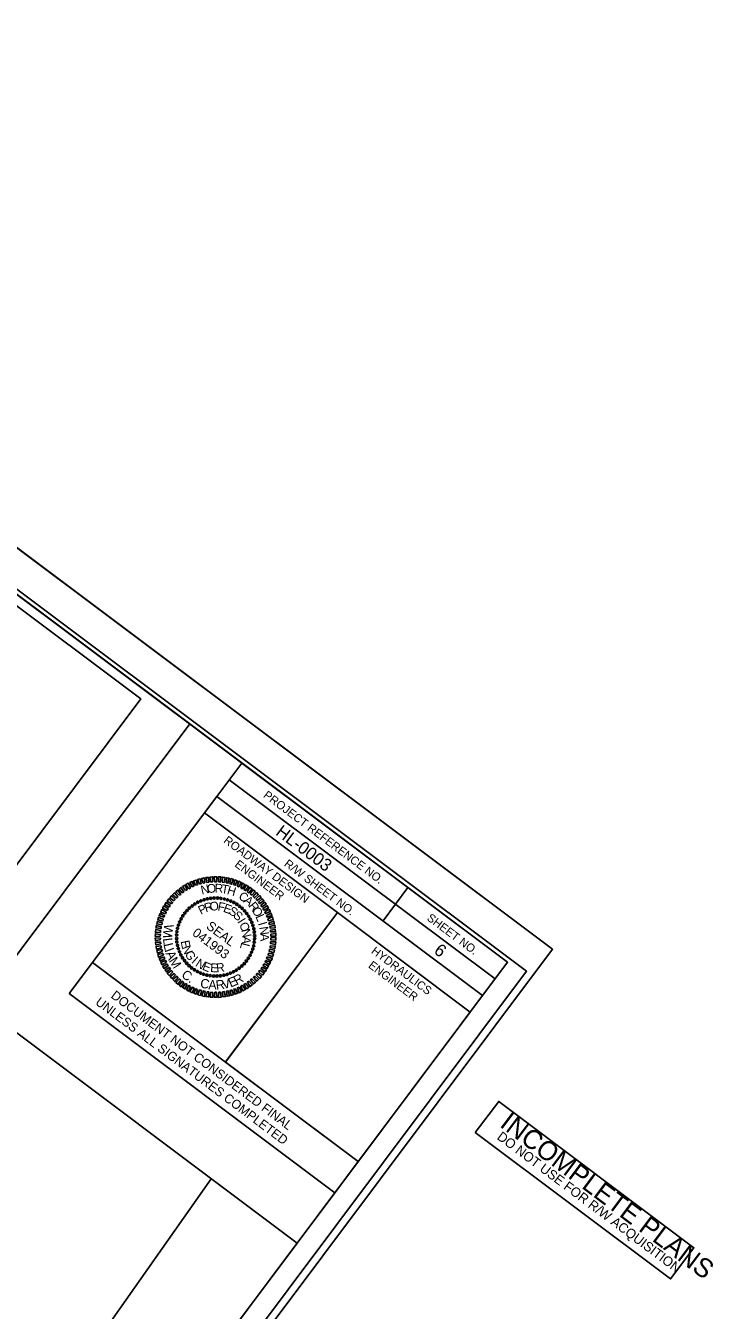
# Model space of a CAD drawing. Extents: x 928111 to 937215, y 684180 to 686530.
# Drawn here: x 931876 to 932290, y 684839 to 685613 of the extents above; entities that cross this region are included whole.
import ezdxf

# ---------------------------------------------------------------- set-up
doc = ezdxf.new("R2010")
doc.units = 0
for name, color, linetype in [('Default', 7, 'Continuous'), ('Matchline', 7, 'Continuous'), ('Prop DSN Text', 7, 'Continuous'), ('Sheet Cutting Line CELL', 7, 'Continuous'), ('Sheet Data Field CELL', 7, 'Continuous'), ('Sheet Layout Plan Border', 7, 'Continuous'), ('Sheet Plan CELL', 7, 'Continuous'), ('Sheet Plan Layout CELL', 7, 'Continuous'), ('Sheet Plot Border Inside CELL', 7, 'Continuous'), ('Sheet Plot Border Outside CELL', 7, 'Continuous')]:
    doc.layers.add(name, color=color, linetype=linetype)

msp = doc.modelspace()

# ---------------------------------------------------------------- linework, layer by layer
at = {"layer": 'Default'}
for p, q in [((931979.89, 685084.68), (931979.89, 685084.68)), ((931981.73, 685085.58), (931981.73, 685085.58)), ((931983.68, 685086.23), (931983.68, 685086.23)), ((931985.68, 685086.78), (931985.68, 685086.78)), ((931987.68, 685087.1), (931987.68, 685087.1)), ((931989.76, 685087.3), (931989.76, 685087.3)), ((931991.77, 685087.25), (931991.77, 685087.25)), ((931993.84, 685087.05), (931993.84, 685087.05)), ((931995.87, 685086.7), (931995.87, 685086.7)), ((931997.82, 685086.18), (931997.82, 685086.18)), ((931999.73, 685085.45), (931999.73, 685085.45)), ((932001.61, 685084.51), (932001.61, 685084.51)), ((931972.04, 685078.2), (931972.04, 685078.2)), ((931973.39, 685079.76), (931973.39, 685079.76)), ((931974.86, 685081.18), (931974.86, 685081.18)), ((931976.38, 685082.5), (931976.38, 685082.5)), ((931978.09, 685083.69), (931978.09, 685083.69)), ((932003.39, 685083.53), (932003.39, 685083.53)), ((932005.07, 685082.33), (932005.07, 685082.33)), ((932006.63, 685080.98), (932006.63, 685080.98)), ((932008.05, 685079.51), (932008.05, 685079.51)), ((932009.37, 685077.99), (932009.37, 685077.99)), ((931967.67, 685069), (931967.67, 685069)), ((931968.19, 685070.95), (931968.19, 685070.95)), ((931968.92, 685072.86), (931968.92, 685072.86)), ((931969.86, 685074.74), (931969.86, 685074.74)), ((931970.84, 685076.52), (931970.84, 685076.52)), ((932010.56, 685076.28), (932010.56, 685076.28)), ((932011.55, 685074.48), (932011.55, 685074.48)), ((932012.45, 685072.64), (932012.45, 685072.64)), ((932013.1, 685070.69), (932013.1, 685070.69)), ((931967.07, 685062.89), (931967.07, 685062.89)), ((931967.12, 685064.9), (931967.12, 685064.9)), ((931967.32, 685066.97), (931967.32, 685066.97)), ((931990.62, 685063.75), (931990.62, 685063.75)), ((932013.65, 685068.69), (932013.65, 685068.69)), ((932013.97, 685066.7), (932013.97, 685066.7)), ((932014.12, 685062.6), (932014.12, 685062.6)), ((932014.17, 685064.61), (932014.17, 685064.61)), ((931967.27, 685060.81), (931967.27, 685060.81)), ((931967.59, 685058.81), (931967.59, 685058.81)), ((931968.14, 685056.81), (931968.14, 685056.81)), ((931968.79, 685054.86), (931968.79, 685054.86)), ((932012.32, 685054.64), (932012.32, 685054.64)), ((932013.05, 685056.55), (932013.05, 685056.55)), ((932013.57, 685058.5), (932013.57, 685058.5)), ((932013.92, 685060.53), (932013.92, 685060.53)), ((931969.69, 685053.02), (931969.69, 685053.02)), ((931970.69, 685051.22), (931970.69, 685051.22)), ((931971.87, 685049.51), (931971.87, 685049.51)), ((931973.19, 685047.99), (931973.19, 685047.99)), ((931974.61, 685046.52), (931974.61, 685046.52)), ((932006.38, 685046.32), (932006.38, 685046.32)), ((932007.85, 685047.74), (932007.85, 685047.74)), ((932009.2, 685049.3), (932009.2, 685049.3)), ((932010.4, 685050.98), (932010.4, 685050.98)), ((932011.38, 685052.76), (932011.38, 685052.76)), ((931976.17, 685045.17), (931976.17, 685045.17)), ((931977.85, 685043.97), (931977.85, 685043.97)), ((931979.63, 685042.99), (931979.63, 685042.99)), ((931981.51, 685042.05), (931981.51, 685042.05)), ((931983.42, 685041.32), (931983.42, 685041.32)), ((931985.37, 685040.8), (931985.37, 685040.8)), ((931987.4, 685040.45), (931987.4, 685040.45)), ((931989.47, 685040.25), (931989.47, 685040.25)), ((931991.48, 685040.2), (931991.48, 685040.2)), ((931993.57, 685040.4), (931993.57, 685040.4)), ((931995.56, 685040.72), (931995.56, 685040.72)), ((931997.56, 685041.27), (931997.56, 685041.27)), ((931999.51, 685041.92), (931999.51, 685041.92)), ((932001.35, 685042.82), (932001.35, 685042.82)), ((932003.15, 685043.82), (932003.15, 685043.82)), ((932004.86, 685045), (932004.86, 685045))]:
    msp.add_line(p, q, dxfattribs=at)
for points in [[(931987.63, 685096.97), (931987.22, 685099.86), (931988.79, 685100.09), (931988.74, 685096.97)], [(931990.01, 685097.01), (931989.74, 685100.02), (931991.34, 685100.05), (931991.08, 685096.97)], [(931992.27, 685097.07), (931992.32, 685100.02), (931993.83, 685100), (931993.44, 685096.9)], [(931994.63, 685096.77), (931994.76, 685099.84), (931996.37, 685099.57), (931995.68, 685096.69)], [(931970.54, 685090.34), (931968.58, 685092.57), (931969.77, 685093.61), (931971.43, 685090.9)], [(931972.45, 685091.72), (931970.63, 685094.13), (931971.99, 685094.93), (931973.45, 685092.2)], [(931974.44, 685092.81), (931972.76, 685095.41), (931974.19, 685096.15), (931975.43, 685093.35)], [(931976.48, 685093.97), (931975.04, 685096.51), (931976.48, 685097.25), (931977.46, 685094.34)], [(931978.59, 685094.91), (931977.33, 685097.61), (931978.87, 685098.09), (931979.69, 685095.13)], [(931980.84, 685095.56), (931979.77, 685098.36), (931981.29, 685098.91), (931981.86, 685095.91)], [(931983.03, 685096.15), (931982.18, 685099.07), (931983.73, 685099.43), (931984.06, 685096.43)], [(931985.41, 685096.59), (931984.65, 685099.56), (931986.24, 685099.72), (931986.46, 685096.74)], [(931996.91, 685096.46), (931997.29, 685099.46), (931998.84, 685099.12), (931997.99, 685096.18)], [(931999.16, 685096.01), (931999.81, 685098.92), (932001.27, 685098.53), (932000.26, 685095.54)], [(932001.44, 685095.24), (932002.27, 685098.13), (932003.68, 685097.6), (932002.43, 685094.91)], [(932003.61, 685094.37), (932004.59, 685097.33), (932006.06, 685096.64), (932004.54, 685093.97)], [(932005.72, 685093.44), (932006.92, 685096.29), (932008.24, 685095.47), (932006.7, 685092.88)], [(932007.69, 685092.31), (932009.07, 685095.02), (932010.46, 685094.22), (932008.67, 685091.75)], [(932009.7, 685091.1), (932011.34, 685093.68), (932012.55, 685092.71), (932010.58, 685090.38)], [(932011.48, 685089.71), (932013.3, 685092.15), (932014.51, 685091.18), (932012.35, 685089)], [(931962.62, 685081.8), (931959.96, 685083.33), (931960.84, 685084.66), (931963.22, 685082.76)], [(931963.99, 685083.71), (931961.46, 685085.42), (931962.42, 685086.7), (931964.66, 685084.61)], [(931965.43, 685085.55), (931963.05, 685087.46), (931964.05, 685088.64), (931966.18, 685086.4)], [(931966.97, 685087.21), (931964.73, 685089.24), (931965.84, 685090.4), (931967.83, 685087.97)], [(931968.7, 685088.9), (931966.6, 685090.95), (931967.82, 685092.02), (931969.59, 685089.47)], [(932013.27, 685088.19), (932015.25, 685090.52), (932016.31, 685089.37), (932014.06, 685087.37)], [(932014.84, 685086.54), (932016.98, 685088.69), (932018.08, 685087.58), (932015.66, 685085.76)], [(932016.45, 685084.7), (932018.65, 685086.85), (932019.7, 685085.6), (932017.1, 685083.92)], [(932017.88, 685082.86), (932020.19, 685084.76), (932021.07, 685083.52), (932018.47, 685082.01)], [(931959.58, 685075.64), (931956.54, 685076.58), (931957.24, 685077.99), (931959.91, 685076.63)], [(931960.48, 685077.78), (931957.59, 685078.84), (931958.32, 685080.28), (931960.85, 685078.74)], [(931961.49, 685079.83), (931958.66, 685081.14), (931959.51, 685082.5), (931962.02, 685080.85)], [(932019.07, 685080.92), (932021.7, 685082.64), (932022.41, 685081.4), (932019.73, 685080.01)], [(932020.22, 685078.94), (932022.82, 685080.45), (932023.59, 685079.06), (932020.74, 685077.91)], [(932021.3, 685076.79), (932023.91, 685078.17), (932024.56, 685076.68), (932021.67, 685075.8)], [(931957.73, 685068.95), (931954.65, 685069.21), (931955.03, 685070.74), (931957.81, 685070)], [(931958.19, 685071.12), (931955.13, 685071.66), (931955.54, 685073.22), (931958.43, 685072.23)], [(931958.83, 685073.39), (931955.82, 685074.13), (931956.27, 685075.6), (931959.05, 685074.46)], [(932022, 685074.68), (932024.95, 685075.87), (932025.33, 685074.35), (932022.49, 685073.61)], [(932022.7, 685072.4), (932025.63, 685073.42), (932025.99, 685071.87), (932023.02, 685071.34)], [(932023.25, 685070.17), (932026.25, 685070.97), (932026.48, 685069.39), (932023.54, 685069.07)], [(931957.29, 685064.3), (931954.27, 685064.1), (931954.38, 685065.72), (931957.38, 685065.35)], [(931957.32, 685061.99), (931954.33, 685061.6), (931954.3, 685063.2), (931957.36, 685063.14)], [(931957.47, 685066.57), (931954.41, 685066.63), (931954.54, 685068.29), (931957.51, 685067.71)], [(932023.62, 685067.84), (932026.55, 685068.4), (932026.78, 685066.82), (932023.73, 685066.82)], [(932023.95, 685063.2), (932026.97, 685063.4), (932026.87, 685061.78), (932023.86, 685062.15)], [(932023.92, 685065.51), (932026.91, 685065.9), (932026.94, 685064.3), (932023.88, 685064.37)], [(931957.62, 685059.66), (931954.69, 685059.1), (931954.46, 685060.68), (931957.51, 685060.68)], [(931957.99, 685057.33), (931954.99, 685056.53), (931954.76, 685058.11), (931957.7, 685058.43)], [(931958.54, 685055.1), (931955.61, 685054.08), (931955.25, 685055.63), (931958.22, 685056.16)], [(931959.24, 685052.82), (931956.29, 685051.63), (931955.91, 685053.15), (931958.75, 685053.89)], [(932022.41, 685054.11), (932025.43, 685053.37), (932024.97, 685051.9), (932022.19, 685053.04)], [(932023.05, 685056.38), (932026.11, 685055.84), (932025.7, 685054.28), (932022.81, 685055.27)], [(932023.51, 685058.55), (932026.59, 685058.29), (932026.21, 685056.76), (932023.43, 685057.5)], [(932023.77, 685060.93), (932026.83, 685060.87), (932026.7, 685059.21), (932023.73, 685059.79)], [(931959.94, 685050.71), (931957.33, 685049.34), (931956.68, 685050.82), (931959.57, 685051.7)], [(931961.02, 685048.56), (931958.42, 685047.05), (931957.66, 685048.44), (931960.5, 685049.59)], [(931962.18, 685046.58), (931959.54, 685044.86), (931958.83, 685046.1), (931961.51, 685047.49)], [(932018.62, 685045.7), (932021.29, 685044.17), (932020.4, 685042.84), (932018.02, 685044.74)], [(932019.75, 685047.67), (932022.58, 685046.36), (932021.74, 685045.01), (932019.22, 685046.65)], [(932020.76, 685049.72), (932023.66, 685048.66), (932022.92, 685047.22), (932020.39, 685048.76)], [(932021.66, 685051.86), (932024.7, 685050.92), (932024, 685049.52), (932021.33, 685050.87)], [(931963.36, 685044.64), (931961.05, 685042.74), (931960.17, 685043.98), (931962.77, 685045.49)], [(931964.79, 685042.8), (931962.59, 685040.65), (931961.54, 685041.9), (931964.15, 685043.58)], [(931966.4, 685040.96), (931964.26, 685038.81), (931963.16, 685039.93), (931965.58, 685041.75)], [(931967.97, 685039.31), (931966, 685036.98), (931964.93, 685038.14), (931967.18, 685040.13)], [(931969.76, 685037.79), (931967.94, 685035.35), (931966.73, 685036.32), (931968.89, 685038.5)], [(932012.54, 685038.6), (932014.64, 685036.55), (932013.42, 685035.48), (932011.65, 685038.03)], [(932014.27, 685040.29), (932016.51, 685038.26), (932015.4, 685037.1), (932013.41, 685039.53)], [(932015.81, 685041.95), (932018.19, 685040.04), (932017.19, 685038.86), (932015.06, 685041.1)], [(932017.25, 685043.79), (932019.78, 685042.08), (932018.82, 685040.8), (932016.58, 685042.89)], [(931971.54, 685036.4), (931969.9, 685033.83), (931968.69, 685034.79), (931970.66, 685037.12)], [(931973.55, 685035.19), (931972.17, 685032.48), (931970.78, 685033.28), (931972.57, 685035.75)], [(931975.52, 685034.06), (931974.32, 685031.21), (931973, 685032.03), (931974.54, 685034.62)], [(931977.63, 685033.13), (931976.65, 685030.17), (931975.18, 685030.87), (931976.7, 685033.53)], [(931979.8, 685032.26), (931978.97, 685029.37), (931977.56, 685029.9), (931978.81, 685032.59)], [(931982.09, 685031.49), (931981.43, 685028.58), (931979.97, 685028.97), (931980.98, 685031.96)], [(931984.33, 685031.04), (931983.95, 685028.04), (931982.4, 685028.38), (931983.25, 685031.32)], [(931986.61, 685030.73), (931986.48, 685027.66), (931984.87, 685027.94), (931985.56, 685030.81)], [(931988.97, 685030.43), (931988.92, 685027.48), (931987.41, 685027.5), (931987.8, 685030.6)], [(931991.24, 685030.49), (931991.5, 685027.48), (931989.9, 685027.45), (931990.16, 685030.53)], [(931993.61, 685030.53), (931994.02, 685027.64), (931992.45, 685027.41), (931992.5, 685030.54)], [(931995.83, 685030.91), (931996.59, 685027.94), (931995.01, 685027.78), (931994.78, 685030.76)], [(931998.21, 685031.35), (931999.06, 685028.43), (931997.51, 685028.07), (931997.18, 685031.07)], [(932000.4, 685031.94), (932001.47, 685029.14), (931999.95, 685028.59), (931999.38, 685031.59)], [(932002.65, 685032.59), (932003.91, 685029.89), (932002.37, 685029.41), (932001.55, 685032.37)], [(932004.76, 685033.53), (932006.2, 685030.99), (932004.76, 685030.25), (932003.78, 685033.16)], [(932006.81, 685034.7), (932008.48, 685032.09), (932007.05, 685031.35), (932005.81, 685034.15)], [(932008.79, 685035.78), (932010.61, 685033.37), (932009.25, 685032.57), (932007.79, 685035.3)], [(932010.7, 685037.16), (932012.66, 685034.93), (932011.47, 685033.89), (932009.81, 685036.6)]]:
    msp.add_lwpolyline(points, close=True, dxfattribs=at)
for centre, major_axis in [((931978.11, 685083.66), (-0.359, 0.571)), ((931979.89, 685084.67), (-0.308, 0.601)), ((931981.75, 685085.53), (-0.255, 0.625)), ((931983.68, 685086.22), (-0.199, 0.645)), ((931985.67, 685086.74), (-0.142, 0.66)), ((931987.69, 685087.08), (-0.084, 0.67)), ((931989.74, 685087.25), (-0.025, 0.675)), ((931991.79, 685087.23), (0.033, 0.674)), ((931993.83, 685087.04), (0.092, 0.669)), ((931995.85, 685086.67), (0.15, 0.658)), ((931997.83, 685086.13), (0.207, 0.643)), ((931999.75, 685085.42), (0.262, 0.622)), ((932001.6, 685084.54), (0.315, 0.597)), ((931970.87, 685076.5), (-0.567, 0.366)), ((931972.05, 685078.18), (-0.533, 0.414)), ((931973.38, 685079.74), (-0.495, 0.459)), ((931974.84, 685081.18), (-0.453, 0.5)), ((931976.42, 685082.49), (-0.408, 0.538)), ((932003.37, 685083.5), (0.366, 0.567)), ((932005.05, 685082.32), (0.414, 0.533)), ((932006.61, 685080.99), (0.459, 0.495)), ((932008.05, 685079.53), (0.5, 0.453)), ((932009.36, 685077.95), (0.538, 0.408)), ((932010.53, 685076.26), (0.571, 0.359)), ((931967.7, 685068.98), (-0.658, 0.15)), ((931968.24, 685070.96), (-0.643, 0.207)), ((931968.95, 685072.88), (-0.622, 0.262)), ((931969.83, 685074.73), (-0.597, 0.315)), ((932011.54, 685074.48), (0.601, 0.308)), ((932012.4, 685072.62), (0.625, 0.255)), ((932013.09, 685070.69), (0.645, 0.199)), ((932013.61, 685068.7), (0.66, 0.142)), ((931967.14, 685064.92), (-0.674, 0.033)), ((931967.12, 685062.87), (-0.675, -0.025)), ((931967.29, 685060.82), (-0.67, -0.084)), ((931967.33, 685066.96), (-0.669, 0.092)), ((932013.91, 685060.54), (0.669, -0.092)), ((932013.95, 685066.68), (0.67, 0.084)), ((932014.1, 685062.58), (0.674, -0.033)), ((932014.12, 685064.63), (0.675, 0.025)), ((931967.64, 685058.8), (-0.66, -0.142)), ((931968.15, 685056.81), (-0.645, -0.199)), ((931968.84, 685054.88), (-0.625, -0.255)), ((931969.7, 685053.02), (-0.601, -0.308)), ((932011.41, 685052.77), (0.597, -0.315)), ((932012.29, 685054.62), (0.622, -0.262)), ((932013, 685056.55), (0.643, -0.207)), ((932013.54, 685058.52), (0.658, -0.15)), ((931970.71, 685051.24), (-0.571, -0.359)), ((931971.88, 685049.55), (-0.538, -0.408)), ((931973.19, 685047.97), (-0.5, -0.453)), ((931974.63, 685046.51), (-0.459, -0.495)), ((931976.2, 685045.18), (-0.414, -0.533)), ((932004.82, 685045.01), (0.408, -0.538)), ((932006.4, 685046.32), (0.453, -0.5)), ((932007.86, 685047.76), (0.495, -0.459)), ((932009.19, 685049.33), (0.533, -0.414)), ((932010.37, 685051), (0.567, -0.366)), ((931977.87, 685044), (-0.366, -0.567)), ((931979.64, 685042.96), (-0.315, -0.597)), ((931981.49, 685042.08), (-0.262, -0.622)), ((931983.42, 685041.37), (-0.207, -0.643)), ((931985.39, 685040.83), (-0.15, -0.658)), ((931987.41, 685040.46), (-0.092, -0.669)), ((931989.45, 685040.27), (-0.033, -0.674)), ((931991.51, 685040.25), (0.025, -0.675)), ((931993.55, 685040.42), (0.084, -0.67)), ((931995.57, 685040.76), (0.142, -0.66)), ((931997.56, 685041.28), (0.199, -0.645)), ((931999.49, 685041.97), (0.255, -0.625)), ((932001.35, 685042.83), (0.308, -0.601)), ((932003.13, 685043.84), (0.359, -0.571))]:
    msp.add_ellipse(centre, major_axis=major_axis, ratio=0.999708, dxfattribs=at)
at = {"layer": 'Matchline'}
msp.add_line((931505.26, 684232.03), (931987.94, 684918.14), dxfattribs=at)
at = {"layer": 'Prop DSN Text'}
msp.add_lwpolyline([(931684.84, 685402.44), (931945.48, 685207.14), (931826.18, 685047.92), (931565.53, 685243.22)], close=True, dxfattribs=at)
at = {"layer": 'Sheet Cutting Line CELL'}
msp.add_line((932193.6, 685056.42), (930846.34, 686065.9), dxfattribs=at)
at = {"layer": 'Sheet Layout Plan Border'}
msp.add_line((931987.94, 684918.14), (931505.26, 684232.03), dxfattribs=at)
at = {"layer": 'Sheet Plan CELL'}
for p, q in [((931998.89, 685158.54), (932158.97, 685038.58)), ((931991.38, 685148.5), (931983.89, 685138.51)), ((931991.38, 685148.5), (932151.48, 685028.57)), ((931991.38, 685148.5), (932151.48, 685028.57)), ((932106.42, 685093.56), (932091.47, 685073.52)), ((932063.96, 685078.52), (931996.53, 684988.51)), ((931902.36, 685029.67), (931916.45, 685048.48)), ((931916.45, 685048.48), (932076.53, 684928.53)), ((932062.44, 684909.73), (931902.36, 685029.67)), ((932076.53, 684928.52), (932062.43, 684909.72))]:
    msp.add_line(p, q, dxfattribs=at)
for points in [[(932166.53, 685048.6), (930966.09, 685948.07), (930336.47, 685107.79), (931536.89, 684208.33)], [(931848.22, 685022.84), (932039.7, 684879.36), (932166.54, 685048.59), (931975.03, 685192.08)], [(932006.42, 685168.58), (932166.53, 685048.6), (932151.48, 685028.57), (931991.38, 685148.5)], [(931983.89, 685138.51), (932063.96, 685078.52), (931996.49, 684988.48), (931916.45, 685048.48)], [(932063.96, 685078.52), (932143.98, 685018.57), (932076.53, 684928.52), (931996.49, 684988.48)], [(932147.06, 684945.96), (932161.15, 684964.76), (932278.79, 684876.62), (932264.7, 684857.81)]]:
    msp.add_lwpolyline(points, close=True, dxfattribs=at)
at = {"layer": 'Sheet Plan Layout CELL'}
msp.add_lwpolyline([(930966.05, 685948.07), (930336.47, 685107.79), (931536.88, 684208.33), (932039.68, 684879.37), (931848.22, 685022.84), (931975.03, 685192.08)], close=True, dxfattribs=at)
at = {"layer": 'Sheet Plot Border Inside CELL'}
msp.add_lwpolyline([(930212.13, 685197.81), (931545.39, 684198.84), (932178, 685043.11), (930844.75, 686042.1)], close=True, dxfattribs=at)
at = {"layer": 'Sheet Plot Border Outside CELL'}
msp.add_lwpolyline([(930189.74, 685189.6), (931537, 684180.12), (932193.6, 685056.42), (930846.34, 686065.9)], close=True, dxfattribs=at)

# ---------------------------------------------------------------- texts
at = {"layer": 'Default'}
for s, height, rotation, p in [('N', 5.29, 12.57973, (931982.3, 685089.31)), ('O', 5.29, 5.37797, (931985.66, 685090.19)), ('R', 5.29, 358.17674, (931989.99, 685090.58)), ('T', 5.29, 350.976, (931993.78, 685090.32)), ('H', 5.29, 343.77571, (931997.14, 685089.73)), ('R', 5.29, 17.19588, (931984.74, 685078.58)), ('O', 5.29, 7.83747, (931987.44, 685079.43)), ('F', 5.29, 349.12326, (931991.57, 685079.79)), ('C', 5.29, 329.3761, (932003.97, 685086.96)), ('A', 5.29, 322.17655, (932007.1, 685084.96)), ('R', 5.29, 307.77733, (932010.14, 685082.45)), ('P', 5.29, 26.55512, (931981.75, 685077.08)), ('E', 5.29, 339.7673, (931994.81, 685079.12)), ('S', 5.29, 330.41184, (931997.99, 685077.97)), ('S', 5.29, 321.05663, (932000.72, 685075.98)), ('O', 5.29, 300.57739, (932012.23, 685080.01)), ('L', 5.29, 293.3771, (932014.49, 685076.15)), ('W', 5.62, 261.51363, (931959.88, 685071.83)), ('041993', 5.623, 323.15623, (931976.13, 685065.22)), ('SEAL', 5.623, 323.15623, (931984.5, 685069.33)), ('I', 5.29, 302.34583, (932003.55, 685073.04)), ('O', 5.29, 292.98971, (932004.66, 685071.39)), ('I', 5.29, 286.17637, (932016.18, 685072.07)), ('N', 5.29, 278.97514, (932016.92, 685069.7)), ('I', 5.62, 274.0477, (931958.86, 685064.97)), ('L', 5.62, 277.84965, (931958.85, 685062.86)), ('E', 5.29, 281.43312, (931969.52, 685061.23)), ('N', 5.29, 283.63284, (932006.05, 685068)), ('A', 5.29, 264.9165, (932006.73, 685064.45)), ('A', 5.29, 271.77338, (932017.48, 685065.83)), ('L', 5.62, 284.12441, (931959.14, 685059.39)), ('I', 5.62, 290.39918, (931959.8, 685055.98)), ('A', 5.62, 294.20113, (931960.39, 685053.95)), ('N', 5.29, 290.79019, (931970.25, 685057.52)), ('G', 5.29, 300.14647, (931971.84, 685053.69)), ('L', 5.29, 255.55708, (932006.25, 685060.77)), ('M', 5.62, 303.04144, (931962.25, 685049.42)), ('I', 5.29, 318.85743, (931975.68, 685048.58)), ('N', 5.29, 328.21262, (931978.11, 685046.59)), ('E', 5.29, 337.56799, (931982.16, 685044.26)), ('E', 5.29, 356.28032, (931987.24, 685042.74)), ('R', 5.29, 5.63764, (931991.22, 685042.51)), ('C', 5.62, 324.77129, (931969.57, 685039.94)), ('C', 5.62, 348.58757, (931980.98, 685033.46)), ('R', 5.62, 7.01003, (931991.05, 685031.97)), ('V', 5.62, 14.49029, (931995.18, 685032.3)), ('E', 5.62, 22.74331, (931999.65, 685033.28)), ('R', 5.62, 29.85265, (932003.35, 685034.63)), ('.', 5.62, 334.35344, (931973.83, 685036.76)), ('A', 5.62, 358.16972, (931986.16, 685032.28))]:
    msp.add_text(s, height=height, rotation=rotation, dxfattribs=at).set_placement(p)
at = {"layer": 'Sheet Data Field CELL'}
for s, p in [('HL-0003', (932026.3, 685125.79)), ('6', (932121.59, 685054.46))]:
    msp.add_text(s, height=7.5, rotation=323.15623, dxfattribs=at).set_placement(p)
at = {"layer": 'Sheet Plan CELL'}
for s, height, p in [('PROJECT REFERENCE NO.', 5.0001, (932018.96, 685148.29)), ('ROADWAY DESIGN', 5.0001, (931995.02, 685121.05)), ('ENGINEER', 5, (932001.69, 685106.63)), ('R/W SHEET NO.', 5.0001, (932031.48, 685106.97)), ('SHEET NO.', 5, (932117.45, 685074.34)), ('HYDRAULICS', 5, (932083.97, 685054.43)), ('ENGINEER', 5, (932082.21, 685045.8)), ('DOCUMENT NOT CONSIDERED FINAL', 5.5, (931927.11, 685027.57)), ('UNLESS ALL SIGNATURES COMPLETED', 5.5, (931917.77, 685023.57)), ('INCOMPLETE PLANS', 11.52, (932161.24, 684949.95)), ('DO NOT USE FOR R/W ACQUISITION', 5.76, (932159.67, 684942.44))]:
    msp.add_text(s, height=height, rotation=323.15623, dxfattribs=at).set_placement(p)

doc.saveas('drawing.dxf')
